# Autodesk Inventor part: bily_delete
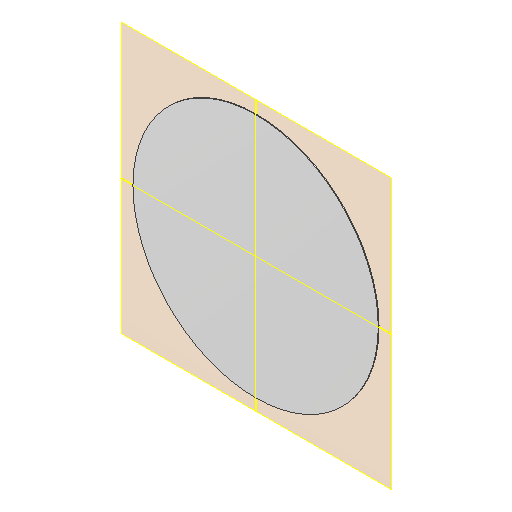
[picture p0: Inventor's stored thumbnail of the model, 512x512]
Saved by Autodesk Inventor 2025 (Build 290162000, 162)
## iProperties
Created: 2025-03
Part Number: bily_delete
Material: UHMW, White
Document SubType Name: Modeling
Designer: dansp
Mass: 4.98335e-05 g
Surface Area: 0.107442 cm^2
Volume: 5.30144e-05 cm^3
Density: 0.94 g/cm^3
Appearance: Smooth - White
Author: dansp
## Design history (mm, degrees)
sketch "Sketch1"
  geometry: C1 r 1.54 at (0, 0); C2 r 0.75 at (0, 0); 1 further point
  constraints: 2 centre point, 2 coincident
  dimensions: "d0" = 3.08 diameter of C1; "d1" = 1.5 diameter of C2
extrude "Extrusion1" new body sketch "Sketch1" distance "d2" = 0.01; taper "d3" = 0 deg
body "Solid1"
